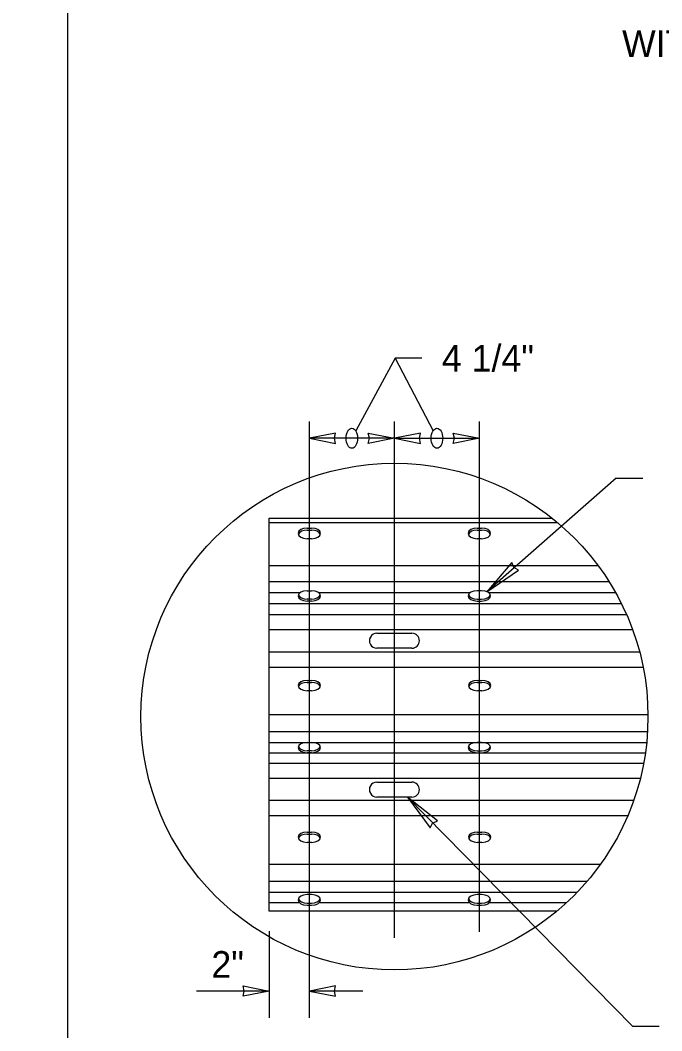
# Model space of a CAD drawing. Extents: x 34446 to 262144, y 33903 to 262144.
# Drawn here: x 99834 to 100218, y 100311 to 100918 of the extents above; entities that cross this region are included whole.
import ezdxf

# ---------------------------------------------------------------- set-up
doc = ezdxf.new("R2010")
doc.units = 0
for name, color, linetype in [('Level 1', 7, 'Continuous'), ('Level 12', 7, 'Continuous'), ('Level 15', 7, 'Continuous'), ('Level 20', 7, 'Continuous'), ('Level 5', 7, 'Continuous'), ('Level 9', 7, 'Continuous')]:
    doc.layers.add(name, color=color, linetype=linetype)

msp = doc.modelspace()

# ---------------------------------------------------------------- linework, layer by layer
at = {"layer": 'Level 1'}
msp.add_lwpolyline([(99862, 99999.5), (103151, 99999.5), (103151, 102075.5), (99862, 102075.5)], close=True, dxfattribs=at)
at = {"layer": 'Level 12'}
for p, q in [((99983.03670781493, 100383.21496457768), (99983.03670781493, 100618.92587069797)), ((99983.03670781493, 100618.92587069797), (100152.65828689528, 100618.92587069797)), ((100155.45786151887, 100383.21496457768), (99983.0367078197, 100383.21496457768))]:
    msp.add_line(p, q, dxfattribs=at)
for points in [[(100047.53670886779, 100549.90312076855), (100068.53670676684, 100549.90312076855)], [(100068.53670676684, 100540.94880604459), (100047.53670886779, 100540.94880604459)], [(100047.53670886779, 100460.61526847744), (100068.53670676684, 100460.61526847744)], [(100068.53670676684, 100451.66095375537), (100047.53670886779, 100451.66095375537)]]:
    msp.add_lwpolyline(points, dxfattribs=at)
for centre, start_param, end_param in [((100047.53670886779, 100545.42596340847), 4.71238898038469, 7.853981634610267), ((100068.53670676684, 100545.42596340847), 1.5707963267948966, 4.71238898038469), ((100047.53670886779, 100456.13811111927), 4.71238898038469, 7.853981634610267), ((100068.53670676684, 100456.13811111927), 1.5707963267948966, 4.71238898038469)]:
    msp.add_ellipse(centre, major_axis=(-4.499999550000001, 5.510910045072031e-16), ratio=0.9949239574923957, start_param=start_param, end_param=end_param, dxfattribs=at)
at = {"layer": 'Level 15'}
for p, q in [((100058.53670781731, 100714.92587069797), (100034.9068826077, 100671.3015780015)), ((100074.53670781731, 100714.92587069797), (100058.53670781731, 100714.92587069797)), ((100058.53670781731, 100714.92587069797), (100081.21634940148, 100671.38095885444)), ((100007.03670781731, 100319.21496457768), (100007.03670781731, 100677.01642495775)), ((100058.03670781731, 100367.21496457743), (100058.03670781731, 100677.01642495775)), ((100109.03670781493, 100370.75812382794), (100109.03670781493, 100677.01642495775)), ((100058.03670781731, 100666.92587069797), (100007.0367078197, 100666.92587069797)), ((100058.03670781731, 100666.92587069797), (100109.03670781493, 100666.92587069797)), ((100191.05065474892, 100642.98191339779), (100113.41759815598, 100574.85806452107)), ((100191.05065474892, 100642.98191339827), (100207.05065474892, 100642.98191339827)), ((100065.79137185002, 100451.66095375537), (100200.69492535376, 100314.11618102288)), ((99983.0367078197, 100371.21496457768), (99983.0367078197, 100319.21496457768)), ((99983.0367078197, 100335.21496457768), (99939.41751321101, 100335.21496457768)), ((100039.03670781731, 100335.21496457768), (100007.03670781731, 100335.21496457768)), ((100200.69492535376, 100314.11618102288), (100216.69492535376, 100314.11618102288))]:
    msp.add_line(p, q, dxfattribs=at)
for points in [[(100007.0367078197, 100666.92587069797), (100022.7617078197, 100663.84187069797), (100022.0337078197, 100666.92587069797), (100022.7617078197, 100670.00987069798)], [(100058.03670781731, 100666.92587069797), (100042.31170781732, 100663.84187069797), (100043.03970781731, 100666.92587069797), (100042.31170781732, 100670.00987069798)], [(100058.03670781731, 100666.92587069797), (100073.76170781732, 100663.84187069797), (100073.03370781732, 100666.92587069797), (100073.76170781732, 100670.00987069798)], [(100109.03670781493, 100666.92587069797), (100093.31170781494, 100663.84187069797), (100094.03970781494, 100666.92587069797), (100093.31170781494, 100670.00987069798)], [(100113.41759815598, 100574.85806452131), (100132.43995917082, 100587.828155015), (100129.66481363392, 100589.35259860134), (100128.46640838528, 100592.28369035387)], [(100065.79137184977, 100451.66095375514), (100079.48054454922, 100433.14933532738), (100080.89757511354, 100435.98083411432), (100083.78061438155, 100437.29062744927)], [(99983.0367078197, 100335.21496457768), (99967.3117078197, 100332.13096457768), (99968.0397078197, 100335.21496457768), (99967.3117078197, 100338.29896457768)], [(100007.03670781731, 100335.21496457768), (100022.76170781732, 100332.13096457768), (100022.03370781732, 100335.21496457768), (100022.76170781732, 100338.29896457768)]]:
    msp.add_lwpolyline(points, close=True, dxfattribs=at)
msp.add_circle((100058.08498716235, 100499.93053054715), 152, dxfattribs=at)
for centre in [(100032.53670781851, 100666.92587069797), (100083.53670781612, 100666.92587069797)]:
    msp.add_ellipse(centre, major_axis=(-9.648735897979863e-16, -5.999999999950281), ratio=0.5773502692, dxfattribs=at)
at = {"layer": 'Level 5'}
msp.add_spline([(100965.33493063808, 100576.21973024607), (100979.73117748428, 100581.07419127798), (100976.64599230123, 100587.06308016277), (100980.63858489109, 100590.14826534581), (100978.82377007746, 100594.86678386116), (100978.82377007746, 100594.86678386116), (100972.34760629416, 100605.2602740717)], degree=3, dxfattribs=at)
at = {"layer": 'Level 9'}
for p, q in [((99983.03670781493, 100616.2722276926), (100155.90425676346, 100616.2722276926)), ((100005.73087043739, 100613.01363668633), (100008.34254519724, 100613.01363668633)), ((100005.73087043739, 100611.80601726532), (100008.34254519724, 100611.80601726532)), ((100107.73087043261, 100613.01362813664), (100110.34254519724, 100613.01362813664)), ((100107.73087043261, 100611.80600871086), (100110.34254519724, 100611.80600871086)), ((100008.34254519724, 100606.65645717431), (100005.73087043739, 100606.65645717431)), ((100110.34254519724, 100606.6564486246), (100107.73087043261, 100606.6564486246)), ((99983.03670781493, 100590.65122409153), (100180.04299535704, 100590.65122409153)), ((99983.03670781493, 100580.95281983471), (100186.69054162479, 100580.95281983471)), ((99983.03670781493, 100574.3655025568), (100001.67859690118, 100574.3655025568)), ((100005.73087043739, 100575.40300899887), (100008.34254519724, 100575.40300899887)), ((100012.39481873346, 100574.3655025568), (100103.67861021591, 100574.3655025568)), ((100110.34254519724, 100575.40300044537), (100107.73087043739, 100575.40300044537)), ((100114.39480541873, 100574.3655025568), (100190.6120973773, 100574.3655025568)), ((99983.03670781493, 100567.77818527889), (100194.10224984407, 100567.77818527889)), ((100008.34254519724, 100570.46250035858), (100005.73087043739, 100570.46250035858)), ((100008.34254519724, 100569.25453786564), (100005.73087043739, 100569.25453786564)), ((100107.73087043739, 100570.46249180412), (100110.34254519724, 100570.46249180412)), ((100107.73087043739, 100569.25452930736), (100110.34254519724, 100569.25452930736)), ((99983.03670781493, 100561.19086812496), (100197.19347374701, 100561.19086812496)), ((99983.03670781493, 100552.10074634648), (100200.85146986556, 100552.10074634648)), ((99983.03670781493, 100538.75106425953), (100205.04405004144, 100538.75106425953)), ((99983.03670781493, 100529.66094236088), (100207.14907610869, 100529.66094236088)), ((100005.73087043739, 100521.59738894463), (100008.34254519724, 100521.59738894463)), ((100005.73087043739, 100520.38942644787), (100008.34254519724, 100520.38942644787)), ((100107.8274291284, 100521.5973975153), (100110.43910389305, 100521.5973975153)), ((100107.8274291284, 100520.38943502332), (100110.43910389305, 100520.38943502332)), ((100008.34254519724, 100515.4489178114), (100005.73087043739, 100515.4489178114)), ((100110.43910389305, 100515.44892638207), (100107.8274291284, 100515.44892638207)), ((100210.0807126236, 100501.07046104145), (99983.03670781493, 100501.07046104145)), ((100209.8084053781, 100490.76514103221), (99983.03670781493, 100490.76514103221)), ((99983.03670781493, 100484.46351612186), (100209.29600350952, 100484.46351612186)), ((100005.73087043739, 100484.41213471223), (100008.34254519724, 100484.41213471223)), ((100110.34254519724, 100484.41212615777), (100107.73087043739, 100484.41212615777)), ((99983.03670781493, 100478.16189121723), (100208.51811629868, 100478.16189121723)), ((100008.34254519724, 100479.47162607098), (100005.73087043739, 100479.47162607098)), ((100008.34254519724, 100478.26366357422), (100005.73087043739, 100478.26366357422)), ((100107.73087043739, 100479.47161751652), (100110.34254519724, 100479.47161751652)), ((100107.73087043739, 100478.26365501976), (100110.34254519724, 100478.26365501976)), ((100207.47059646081, 100471.86026630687), (99983.03670781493, 100471.86026630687)), ((100205.47190504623, 100462.76742469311), (99983.03670781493, 100462.76742469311)), ((100201.47828241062, 100449.5086813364), (99983.03670781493, 100449.5086813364)), ((100197.94921266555, 100440.41583971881), (99983.03670781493, 100440.41583971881)), ((100005.73087043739, 100430.60651465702), (100008.34254519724, 100430.60651465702)), ((100005.73087043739, 100429.39855216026), (100008.34254519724, 100429.39855216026)), ((100107.92398781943, 100430.606540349), (100110.53566258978, 100430.606540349)), ((100107.92398781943, 100429.3985778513), (100110.53566258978, 100429.3985778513)), ((100008.34254519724, 100424.45804351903), (100005.73087043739, 100424.45804351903)), ((100110.53566258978, 100424.45806921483), (100107.92398781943, 100424.45806921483)), ((100181.50254945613, 100411.20564498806), (99983.03670781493, 100411.20564498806)), ((100173.39768544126, 100400.90032497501), (99983.03670781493, 100400.90032497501)), ((99983.03670781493, 100394.59870007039), (100167.67150772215, 100394.59870007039)), ((100008.34254519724, 100393.11530334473), (100005.73087043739, 100393.11530334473)), ((100110.34254519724, 100393.11529479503), (100107.73087043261, 100393.11529479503)), ((99983.03670781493, 100388.29707516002), (100001.0962870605, 100388.29707516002)), ((100005.73087043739, 100387.9657432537), (100008.34254519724, 100387.9657432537)), ((100005.73087043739, 100386.75812382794), (100008.34254519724, 100386.75812382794)), ((100012.97712857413, 100388.29707516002), (100103.09627829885, 100388.29707516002)), ((100107.73087043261, 100387.96573470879), (100110.34254519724, 100387.96573470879)), ((100107.73087043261, 100386.75811528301), (100110.34254519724, 100386.75811528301)), ((100114.977137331, 100388.29707516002), (100161.24491949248, 100388.29707516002))]:
    msp.add_line(p, q, dxfattribs=at)
for centre, major_axis, ratio, start_param, end_param in [((100005.73087043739, 100609.8350469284), (-5.409897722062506, 6.625213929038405e-16), 0.5875508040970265, 4.71238898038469, 7.853981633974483), ((100005.73087043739, 100608.62742750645), (-5.409897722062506, 6.625213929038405e-16), 0.5875508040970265, 4.71238898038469, 6.0920623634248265), ((100008.34254519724, 100609.8350469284), (-5.409897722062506, 6.625213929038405e-16), 0.5875508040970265, 1.5707963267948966, 4.71238898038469), ((100008.34254519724, 100608.62742750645), (-5.409897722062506, 6.625213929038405e-16), 0.5875508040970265, 3.3327155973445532, 4.71238898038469), ((100107.73087043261, 100609.83503837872), (-5.409897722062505, 6.625213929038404e-16), 0.5875508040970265, 4.71238898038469, 7.853981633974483), ((100107.73087043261, 100608.62741895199), (-5.409897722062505, 6.625213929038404e-16), 0.5875508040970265, 4.71238898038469, 6.092062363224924), ((100110.34254519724, 100609.83503837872), (-5.409897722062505, 6.625213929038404e-16), 0.5875508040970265, 1.5707963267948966, 4.71238898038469), ((100110.34254519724, 100608.62741895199), (-5.409897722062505, 6.625213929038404e-16), 0.5875508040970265, 3.332715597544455, 4.71238898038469), ((100005.73087043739, 100572.32877343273), (-5.409897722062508, 6.625213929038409e-16), 0.5682613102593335, 4.71238898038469, 7.853981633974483), ((100005.73087043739, 100573.53673592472), (-5.409897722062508, 6.625213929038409e-16), 0.5682613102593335, 0.19775186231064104, 1.5707963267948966), ((100008.34254519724, 100572.32877343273), (-5.409897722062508, 6.625213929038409e-16), 0.5682613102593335, 1.5707963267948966, 4.71238898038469), ((100008.34254519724, 100573.53673592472), (-5.409897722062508, 6.625213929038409e-16), 0.5682613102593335, 1.5707963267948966, 2.943840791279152), ((100107.73087043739, 100572.32876487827), (-5.409897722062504, 6.625213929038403e-16), 0.5682613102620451, 4.71238898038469, 7.853981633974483), ((100107.73087043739, 100573.53672737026), (-5.409897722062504, 6.625213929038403e-16), 0.5682613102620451, 0.19775186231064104, 1.5707963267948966), ((100110.34254519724, 100572.32876487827), (-5.409897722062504, 6.625213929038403e-16), 0.5682613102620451, 1.5707963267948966, 4.71238898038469), ((100110.34254519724, 100573.53672737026), (-5.409897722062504, 6.625213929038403e-16), 0.5682613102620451, 1.5707963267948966, 2.943840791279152), ((100005.73087043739, 100518.52315337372), (5.409897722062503, -1.3417963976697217e-15), 0.5682613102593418, 1.5707963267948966, 4.71238898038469), ((100005.73087043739, 100517.315190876), (5.409897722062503, -1.3417963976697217e-15), 0.5682613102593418, 1.5707963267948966, 2.9438407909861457), ((100008.34254519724, 100518.52315337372), (5.409897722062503, -1.3417963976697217e-15), 0.5682613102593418, 4.71238898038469, 7.853981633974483), ((100008.34254519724, 100517.315190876), (5.409897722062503, -1.3417963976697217e-15), 0.5682613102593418, 0.19775186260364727, 1.5707963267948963), ((100107.8274291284, 100518.52316194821), (5.409897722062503, -1.3417963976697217e-15), 0.5682613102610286, 1.5707963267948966, 4.71238898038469), ((100107.8274291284, 100517.31519945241), (5.409897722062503, -1.3417963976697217e-15), 0.5682613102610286, 1.5707963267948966, 2.9438407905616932), ((100110.43910389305, 100518.52316194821), (5.409897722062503, -1.3417963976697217e-15), 0.5682613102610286, 4.71238898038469, 7.853981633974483), ((100110.43910389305, 100517.31519945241), (5.409897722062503, -1.3417963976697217e-15), 0.5682613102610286, 0.1977518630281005, 1.570796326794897), ((100005.73087043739, 100481.33789914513), (-5.409897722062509, 3.0649985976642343e-15), 0.568261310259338, 4.71238898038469, 7.853981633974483), ((100005.73087043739, 100482.54586164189), (-5.409897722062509, 3.0649985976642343e-15), 0.568261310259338, 0.19775186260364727, 1.5707963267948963), ((100008.34254519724, 100481.33789914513), (-5.409897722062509, 3.0649985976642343e-15), 0.568261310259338, 1.5707963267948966, 4.71238898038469), ((100008.34254519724, 100482.54586164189), (-5.409897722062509, 3.0649985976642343e-15), 0.568261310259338, 1.5707963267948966, 2.9438407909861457), ((100107.73087043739, 100481.33789059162), (-5.409897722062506, 3.0649985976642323e-15), 0.5682613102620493, 4.71238898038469, 7.853981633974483), ((100107.73087043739, 100482.54585308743), (-5.409897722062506, 3.0649985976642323e-15), 0.5682613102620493, 0.1977518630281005, 1.570796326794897), ((100110.34254519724, 100481.33789059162), (-5.409897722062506, 3.0649985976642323e-15), 0.5682613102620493, 1.5707963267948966, 4.71238898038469), ((100110.34254519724, 100482.54585308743), (-5.409897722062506, 3.0649985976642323e-15), 0.5682613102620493, 1.5707963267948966, 2.9438407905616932), ((100005.73087043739, 100427.53227909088), (5.409897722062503, -1.3417963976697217e-15), 0.5682613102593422, 1.5707963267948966, 4.71238898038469), ((100005.73087043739, 100426.32431659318), (5.409897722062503, -1.3417963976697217e-15), 0.5682613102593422, 1.5707963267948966, 2.9438407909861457), ((100008.34254519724, 100427.53227909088), (5.409897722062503, -1.3417963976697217e-15), 0.5682613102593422, 4.71238898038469, 7.853981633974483), ((100008.34254519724, 100426.32431659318), (5.409897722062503, -1.3417963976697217e-15), 0.5682613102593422, 0.19775186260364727, 1.5707963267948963), ((100107.92398781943, 100427.53230478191), (5.409897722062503, -1.3417963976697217e-15), 0.5682613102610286, 1.5707963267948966, 4.71238898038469), ((100107.92398781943, 100426.3243422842), (5.409897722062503, -1.3417963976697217e-15), 0.5682613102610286, 1.5707963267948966, 2.943840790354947), ((100110.53566258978, 100427.53230478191), (5.409897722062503, -1.3417963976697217e-15), 0.5682613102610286, 4.71238898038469, 7.853981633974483), ((100110.53566258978, 100426.3243422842), (5.409897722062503, -1.3417963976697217e-15), 0.5682613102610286, 0.1977518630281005, 1.570796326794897), ((100005.73087043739, 100389.93671358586), (5.409897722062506, 0), 0.5875508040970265, 1.5707963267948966, 4.71238898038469), ((100005.73087043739, 100391.14433301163), (5.409897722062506, 0), 0.5875508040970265, 3.3327155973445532, 4.71238898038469), ((100008.34254519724, 100389.93671358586), (5.409897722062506, 0), 0.5875508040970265, 4.71238898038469, 7.853981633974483), ((100008.34254519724, 100391.14433301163), (5.409897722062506, 0), 0.5875508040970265, 4.71238898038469, 6.0920623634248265), ((100107.73087043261, 100389.93670504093), (5.409897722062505, 0), 0.5875508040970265, 1.5707963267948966, 4.71238898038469), ((100107.73087043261, 100391.14432446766), (5.409897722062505, 0), 0.5875508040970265, 3.332715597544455, 4.71238898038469), ((100110.34254519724, 100389.93670504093), (5.409897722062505, 0), 0.5875508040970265, 4.71238898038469, 7.853981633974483), ((100110.34254519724, 100391.14432446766), (5.409897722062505, 0), 0.5875508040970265, 4.71238898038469, 6.092062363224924)]:
    msp.add_ellipse(centre, major_axis=major_axis, ratio=ratio, start_param=start_param, end_param=end_param, dxfattribs=at)

# ---------------------------------------------------------------- texts
at = {"layer": 'Level 20'}
msp.add_text('WITH 6×8 BLOCK', height=16, dxfattribs=at).set_placement((100194.52825228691, 100895.71120916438))
for s, height, p in [('4 1/4" ', 16, (100086.53670781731, 100706.92587069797)), ('2"', 15.999999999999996, (99948.3081921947, 100343.21496457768))]:
    msp.add_text(s, height=height, rotation=360, dxfattribs=at).set_placement(p)

doc.saveas('drawing.dxf')
